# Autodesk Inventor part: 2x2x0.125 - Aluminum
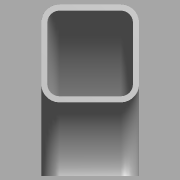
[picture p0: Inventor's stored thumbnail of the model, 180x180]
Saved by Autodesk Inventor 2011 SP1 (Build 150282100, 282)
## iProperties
Created: 2011-03
Part Number: 2x2x0.125 - Aluminum
Material: Default
Document SubType Name: Modeling
Designer: bamfomg
Density: 1 g/cm^3
Author: bamfomg
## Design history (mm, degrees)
derived "Square Tube Corners.ipt" dims "d2" = 25.4, "d3" = 25.4, "d6" = 3.175, "d7" = 3.175, "d8" = 3.175, "d12" = 90 deg, "d16" = 1.5875, "d18" = 30 deg, "ID_Rad" = 6.35, "OD_Rad" = 9.525, "Side_One" = 50.8, "Side_Two" = 50.8, "Thickness" = 3.175, "Bend_IDRad" = 38.1, "Bevel_Angl" = 30 deg, "Bevel_Dist" = 1.5875
body "Solid1"
feature "Solid1::Square Tube Corners.ipt" dims "d2" = 25.4, "d3" = 25.4, "d6" = 3.175, "d7" = 3.175, "d8" = 3.175, "d12" = 90 deg, "d16" = 1.5875, "d18" = 30 deg, "ID_Rad" = 6.35, "OD_Rad" = 9.525, "Side_One" = 50.8, "Side_Two" = 50.8, "Thickness" = 3.175, "Bend_IDRad" = 38.1, "Bevel_Angl" = 30 deg, "Bevel_Dist" = 1.5875, "ScaleForDerivedMember" = 10
tag "TaggingFeature1"
